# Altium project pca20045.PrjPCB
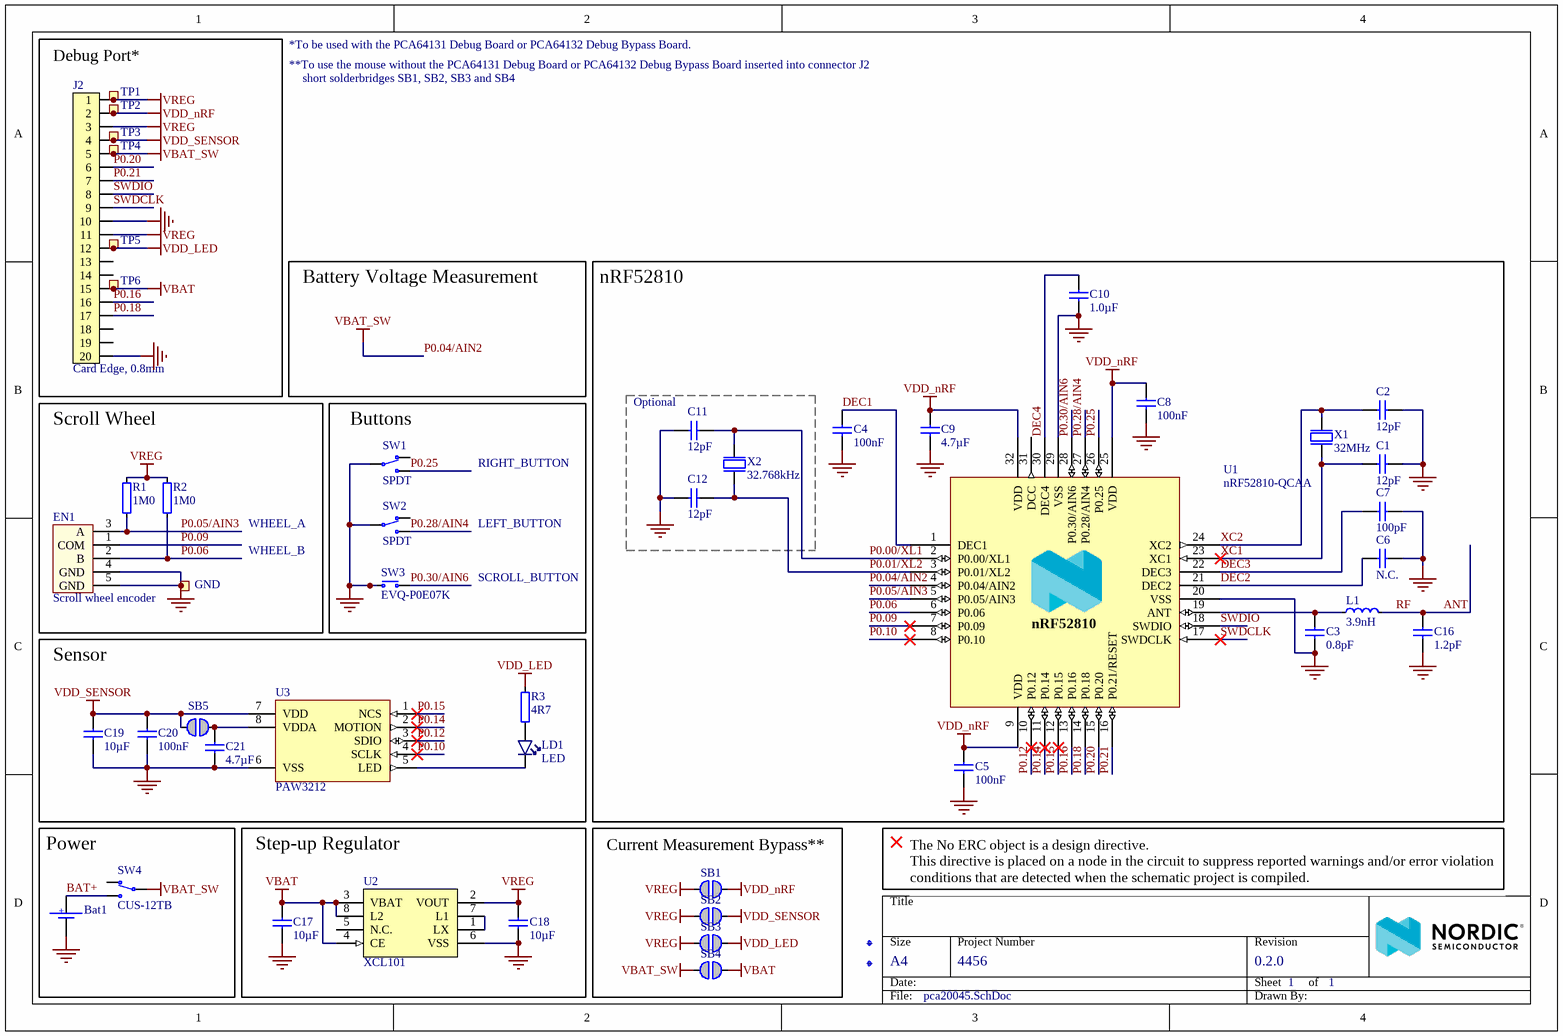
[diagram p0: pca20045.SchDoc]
Author: MASI; BoardThickness: 1.2mm; BoardTitle: nRF52810 QFN32 Desktop Mouse; NrOfLayers: 2; Organization: Nordic Semiconductor; PCAName: PCA20045; PCBNumber: 400448; PCBRevision: 0014MASI; PCBStackup: 2001; ProjectName: nRF52 Desktop; ProjectNumber: 4456; Revision: 0.2.0; SilkscreenColor: White; SoldermaskColor: Blue; SurfaceFinish: Lead-Free HASL
1 sheet, 49 parts. Net scope: global (net labels, ports and power ports of the same name join across sheets).
Board file: 400448.PcbDoc

## Sheet pca20045.SchDoc: =BoardTitle
size A4; Organization: Nordic Semiconductor; Revision: 0.2.0; SheetNumber: 1; SheetTotal: 1; Author: MASI; CompanyName: Nordic Semiconductor; DrawnBy: MASI

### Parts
Bat1  (no value)  [MORFFLUOA_Battery_Spring]
C1  12pF  [CAPC1005X04L]
C2  12pF  [CAPC1005X04L]
C3  0.8pF  [CAPC1005X04L]
C4  100nF  [CAPC1005X04L]
C5  100nF  [CAPC1005X04L]
C6  N.C.  [CAPC1005X04L]
C7  100pF  [CAPC1005X04L]
C8  100nF  [CAPC1005X04L]
C9  4.7µF  [CAPC1608X06L]
C10  1.0µF  [CAPC1608X06L]
C11  12pF  [CAPC1005X04L]
C12  12pF  [CAPC1005X04L]
C16  1.2pF  [CAPC1005X04L]
C17  10µF  [CAPC1608X06L]
C18  10µF  [CAPC1608X06L]
C19  10µF  [CAPC1608X06L]
C20  100nF  [CAPC1608X06L]
C21  4.7µF  [CAPC1608X06L]
EN1  Scroll wheel encoder  [M01_Scroll_Wheel_Encoder]
Fid1  Fiducial mark  [Fiducial]  (value not drawn)
Fid2  Fiducial mark  [Fiducial]  (value not drawn)
GND  TP  [TESTPAD-TH]  (value not drawn)  (no BOM)
J2  Card Edge, 0.8mm  [10056847-101LF]
L1  3.9nH  [INDC1005X04L]
LD1  LED  [LED_5MM_RA]
R1  1M0  [RESC1005X04L]
R2  1M0  [RESC1005X04L]
R3  4R7  [RESC1005X04L]
SB1  Solderbridge  [Solderbridge]  (value not drawn)  (no BOM)
SB2  Solderbridge  [Solderbridge]  (value not drawn)  (no BOM)
SB3  Solderbridge  [Solderbridge]  (value not drawn)  (no BOM)
SB4  Solderbridge  [Solderbridge]  (value not drawn)  (no BOM)
SB5  Solderbridge  [Solderbridge]  (value not drawn)  (no BOM)
SW1  SPDT  [D2F-F]
SW2  SPDT  [D2F-F]
SW3  EVQ-P0E07K  [EVQP0E07K]
SW4  CUS-12TB  [CUS-12B]
TP1  Ø1.5mm,SMD  [TP_SMD_Ø1.5mm]  (value not drawn)  (no BOM)
TP2  Ø1.5mm,SMD  [TP_SMD_Ø1.5mm]  (value not drawn)  (no BOM)
TP3  Ø1.5mm,SMD  [TP_SMD_Ø1.5mm]  (value not drawn)  (no BOM)
TP4  Ø1.5mm,SMD  [TP_SMD_Ø1.5mm]  (value not drawn)  (no BOM)
TP5  Ø1.5mm,SMD  [TP_SMD_Ø1.5mm]  (value not drawn)  (no BOM)
TP6  Ø1.5mm,SMD  [TP_SMD_Ø1.5mm]  (value not drawn)  (no BOM)
U1  nRF52810-QCAA  [Nordic_QFN50P500X500X90-33N]
U2  XCL101  [CL-2025]
U3  PAW3212  [PAW3212DB-TJDT]
X1  32MHz  [BT-XTAL_2016]
X2  32.768kHz  [XTAL_3215]

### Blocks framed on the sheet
Debug Port*: J2 TP1-TP6
nRF52810: C1-C12 C16 L1 U1 X1 X2
Scroll Wheel: EN1 GND R1 R2
Buttons: SW1-SW3
Sensor: C19-C21 LD1 R3 SB5 U3
Power: Bat1 SW4
Step-up Regulator: C17 C18 U2
Current Measurement Bypass**: SB1-SB4

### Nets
GND: Bat1.2 C1.2 C2.2 C3.1 C4.2 C5.2 C6.1 C7.2 C8.2 C9.2 C10.1 C11.2 C12.2 C16.2 C17.1 C18.1 C19.1 C20.1 C21.1 EN1.4(GND) EN1.5(GND) GND.1 J2.10 J2.20 SW1.2(COM) SW2.2(COM) SW3.2(COM) U1.20(VSS) U1.29(VSS) U1.33 U2.6(VSS) U2.9(VSS) U3.6(VSS) X1.2(GND) X1.4(GND)
P0.04/AIN2: J2.5 SB4.1 SW4.2(COM) TP4.1 U1.4(P0.04/AIN2)  [also labelled VBAT_SW]
VBAT: C17.2 J2.15 SB4.2 TP6.1 U2.3(VBAT) U2.4(CE) U2.8(L2)
VDD_LED: J2.12 R3.2 SB3.2 TP5.1
VDD_nRF: C5.1 C8.1 C9.1 J2.2 SB1.2 TP2.1 U1.9(VDD) U1.25(VDD) U1.32(VDD)
VDD_SENSOR: C19.2 C20.2 J2.4 SB2.2 SB5.1 TP3.1 U3.7(VDD)
VREG: C18.2 J2.1 J2.3 J2.11 R1.2 R2.2 SB1.1 SB2.1 SB3.1 TP1.1 U2.2(VOUT)
ANT: C16.1 L1.2  [also labelled RF]
BAT+: Bat1.1 SW4.3(N.O)
DEC1: C4.1 U1.1(DEC1)
DEC2: C6.2 U1.21(DEC2)
DEC3: C7.1 U1.22(DEC3)
DEC4: C10.2 U1.30(DEC4)
P0.00/XL1: C11.1 U1.2(P0.00/XL1) X2.1(inp)
P0.01/XL2: C12.1 U1.3(P0.01/XL2) X2.2(out)
P0.05/AIN3: EN1.3(A) R1.1 U1.5(P0.05/AIN3)
P0.06: EN1.2(B) R2.1 U1.6(P0.06)
P0.09: EN1.1(COM) U1.7(P0.09)
P0.10: U1.8(P0.10) U3.4(SCLK)
P0.12: U1.10(P0.12) U3.3(SDIO)
P0.14: U1.11(P0.14) U3.2(MOTION)
P0.15: U1.12(P0.15) U3.1(NCS)
P0.16: J2.16 U1.13(P0.16)
P0.18: J2.17 U1.14(P0.18)
P0.20: J2.6 U1.15(P0.20)
P0.21: J2.7 U1.16(P0.21/RESET)
P0.25: SW1.3(N.O) U1.26(P0.25)
P0.28/AIN4: SW2.3(N.O) U1.27(P0.28/AIN4)
P0.30/AIN6: SW3.1(N.O) U1.28(P0.30/AIN6)
SWDCLK: J2.9 U1.17(SWDCLK)
SWDIO: J2.8 U1.18(SWDIO)
XC1: C1.1 U1.23(XC1) X1.1(inp)
XC2: C2.1 U1.24(XC2) X1.3(out)
NetC3_2: C3.2 L1.1 U1.19(ANT)
NetC21_2: C21.2 SB5.2 U3.8(VDDA)
NetLD1_1: LD1.1(C) U3.5(LED)
NetLD1_2: LD1.2(A) R3.1
NetU2_1: U2.1(LX) U2.7(L1)

Not connected (* = marked no-connect by the designer): J2 13 14 18 19; SW1 1(N.C); SW2 1(N.C); SW4 1(N.C); U1 31(DCC); U2 5(N.C.)

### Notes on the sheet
- **To use the mouse without the PCA64131 Debug Board or PCA64132 Debug Bypass Board inserted into connector J2
- *To be used with the PCA64131 Debug Board or PCA64132 Debug Bypass Board.
- short solderbridges SB1, SB2, SB3 and SB4
- Battery Voltage Measurement
- (near C11) Optional
- RIGHT_BUTTON
- WHEEL_A
- WHEEL_B
- SCROLL_BUTTON
- LEFT_BUTTON
- The No ERC object is a design directive.
  This directive is placed on a node in the circuit to suppress reported warnings and/or error violation conditions that are detected when the schematic project is compiled.

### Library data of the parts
Bat1 = MORFFLOUA Battery Spring: Battery Spring, 1xAA; Artikkelnr Noca: N.A.
C1 C2 C11 C12 = C0402-12p: Capacitor, NP0, ±2%
C3 = C0402-0.8p: Capacitor, NP0, ±5%
C4 C5 C8 = C0402-100n: Capacitor, X7R, ±10%
C6 = C0402-N.C.: Not mounted; Assembly: Not mounted
C7 = C0402-100p: Capacitor, NP0, ±5%
C9 = C0603-4µ7: Capacitor, X5R, ±10%
C10 = C0603-1µ0: Capacitor, X7R, ±10%
C16 = C0402-1.2p: Capacitor, NP0, ±0.1pF; Part number IPS: 00000005410; Note: 50V; Artikkelnr Noca: 20029157
C17-C19 = C0603-10µ: Capacitor, X5R, ±20%; Part number IPS: 00000007785; Note: 6.3V; Artikkelnr Noca: 20039234
C20 = C0603-100n: Chip Cap 0603; Note: Chip Cap 1%; Artikkelnr Noca: N.A.
C21 = C0603-4µ7: Capacitor, X5R, ±10%; Part number IPS: 00000007783; Note: 6.3V; Artikkelnr Noca: 20069060
EN1 = M01_Scroll_wheel_encoder, 9mm: Scroll wheel encoder, 9mm; Artikkelnr Noca: N.A.
Fid1 Fid2 = Fid-Mark: Artikkelnr Noca: N.A.
GND = Testpoint TH: Testpoint, through hole; Artikkelnr Noca: N.A.
J2 = 10056847-101LF: 0.8mm pitch, dual edge, right angle, SMD, card edge connector; Manufacturer: FCI; Artikkelnr Noca: N.A.
L1 = L0402-3n9: High frequency chip inductor ±5%
LD1 = 7383M-RNW3-APSB: LED, Red, 5mm, Vf=2.0; Manufacturer: Everlight; Artikkelnr Noca: N.A.
R1 R2 = R0402-1M0: Resistor, ±1%, 0.063W; Part number IPS: 00000006807; Note: Chip Res 1%; Artikkelnr Noca: 27049145
R3 = R0402-4R7: Resistor, ±1%, 0.063W; Part number IPS: N.A.; Note: Chip Res 1%; Artikkelnr Noca: 27049017
SB1-SB5 = Solderbridge: Artikkelnr Noca: N.A.
SW1 SW2 = D2F-F: SWITCH SNAP ACTION SPDT 1A 125V; Manufacturer: Omron; Artikkelnr Noca: N.A.
SW3 = EVQ-P0E07K: Switch tactile, SPST-NO, 0.05A, 30V; Manufacturer: Panasonic - ECG; Part number IPS: N.A.; Artikkelnr Noca: 51019119
SW4 = CUS-12TB: Low-profile slide switch, SPDT, ON-ON; Manufacturer: Copal Electronics Inc; Part number IPS: N.A.; Artikkelnr Noca: 50019081
TP1-TP6 = TP_SMD_Ø1.5MM: 1.0mm circular SMD testpad; Manufacturer: Nordic Semiconductor; Artikkelnr Noca: N.A.
U1 = nRF52810-QCAAD0: Multi-protocol Bluetooth Low Energy, ANT and 2.4GHz proprietary system-on-chip; Manufacturer: Nordic Semiconductor; Note: nRF52810 - QFN32 5x5 0.5mm pitch; Artikkelnr Noca: N.A.
U2 = XCL101A211ER-G: Inductor Built-in Step-up “micro DC/DC” Converter, VOUT=2.1V, 100mA; Manufacturer: Torex Semiconductor; Artikkelnr Noca: N.A.
U3 = PAW3212DB-TJDT: Ultra Low Power Wireless Mouse Sensor; Manufacturer: Pixart Imaging inc; Artikkelnr Noca: N.A.
X1 = XTAL_SMD2016_32MHz_8pF_General: XTAL SMD 2016, 32MHz, Cl=8pF, Total Tol: ±40ppm
X2 = XTAL_SMD3215_32.768kHz_9pF_General: XTAL SMD 3215, 32.768kHz, Cl=9pF, Total Tol: ±50ppm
